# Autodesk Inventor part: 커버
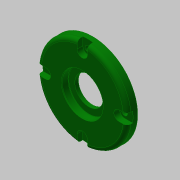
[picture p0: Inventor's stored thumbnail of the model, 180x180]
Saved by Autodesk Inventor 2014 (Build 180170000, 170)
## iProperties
Created: 2020-05
Part Number: 커버
Material: 알루미늄 6061
Document SubType Name: Modeling
Designer: mduedu
Density: 1 g/cm^3
Appearance: Dark Green
d0: 70.000 mm
d2: 47.000 mm
d3: 4.000 mm
d4: 12.000 mm
d8: 22.000 mm
d10: 32.000 mm
d11: 5.200 mm
d17: 40.000 mm
d22: 4.000 mm
d24: 3.000 mm
d25: 3.000 mm
d26: 0.300 mm
d27: 0.500 mm
d29: 30.00 deg
d30: 1.000 mm
d33: 57.000 mm
d34: 8.000 mm
d35: 10.000 mm
d36: 4.400 mm
d37: 0.00 deg
d38: 4.500 mm
d45: 4.000 ul
d46: 360.00 deg
Author: mduedu
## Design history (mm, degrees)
sketch "스케치1"
  geometry: L1 (0, 0)-(8, 0); L2 (8, 0)-(8, 35); L3 (8, 35)-(0, 35); L4 (0, 35)-(0, 0); L5 (8, 0)-(12, 0); L6 (12, 0)-(12, 23.5); L7 (12, 23.5)-(8, 23.5); L8 (8, 23.5)-(8, 0)
  constraints: 16 end point, 4 parallel, 2 horizontal, 2 perpendicular
  dimensions: "d0" = 70 diameter of L3 L1; "d2" = 47 diameter of L7 L5; "d3" = 4 distance of L6.end L7.end; "d4" = 12 distance between parallel lines of L4 L6
revolve "회전1" sketch "스케치1" stored, may be unused: angle "d5" = 90 deg
hole "구멍1" diameter "d8" = 22; stored, may be unused: countersink angle "d12" = 90 deg, drill point angle "d14" = 118 deg; dims "d6" = 10, "d7" = 10, "d9" = 6, "d10" = 32, "d11" = 5.2, "d13" = 8
hole "구멍2" diameter "d17" = 40; stored, may be unused: countersink angle "d21" = 90 deg, drill point angle "d23" = 0 deg; dims "d15" = 10, "d16" = 10, "d18" = 6, "d19" = 32, "d20" = 5.2, "d22" = 4
fillet "모깎기1" dims "d24" = 3
fillet "모깎기2" dims "d25" = 3
fillet "모깎기3" dims "d26" = 0.3
chamfer "모따기1" distance "d27" = 0.5; stored, may be unused: second distance "d28" = 2, angle "d29" = 30 deg
chamfer "모따기2" distance "d30" = 1; stored, may be unused: second distance "d31" = 2, angle "d32" = 30 deg
sketch "스케치2" dims "d33" = 57
  geometry: L1 (-4, 28.5)-(4, 28.5); L2 (4, 28.5)-(4, 38.5); L3 (4, 38.5)-(-4, 38.5); L4 (-4, 38.5)-(-4, 28.5); 4 further points
  constraints: 8 end point, 2 horizontal alignment, 2 midpoint, 2 parallel, 2 vertical alignment, 1 coincident, 1 horizontal, 1 perpendicular, 6 other
  dimensions: "d34" = 8 distance between parallel lines of L2 L4; "d35" = 10 distance of point (0, 28.5) point (0, 38.5)
extrude "돌출1" cut sketch "스케치2" distance "d36" = 4.4; taper "d37" = 0 deg
sketch "스케치3"
  geometry: A1 r 4 centre (0, 28.5) between (-4, 28.5) and (4, 28.5) reference; 2 further points
  constraints: 1 coincident
hole "구멍3" sketch "스케치3" at (0, 28.5) diameter "d38" = 4.5; stored, may be unused: countersink angle "d42" = 90 deg, drill point angle "d44" = 0 deg; dims "d39" = 6, "d40" = 32, "d41" = 5.2, "d43" = 4
node "솔리드1"
pattern_circular "원형 패턴1" dims count "d45" = 4, angle "d46" = 360 deg
